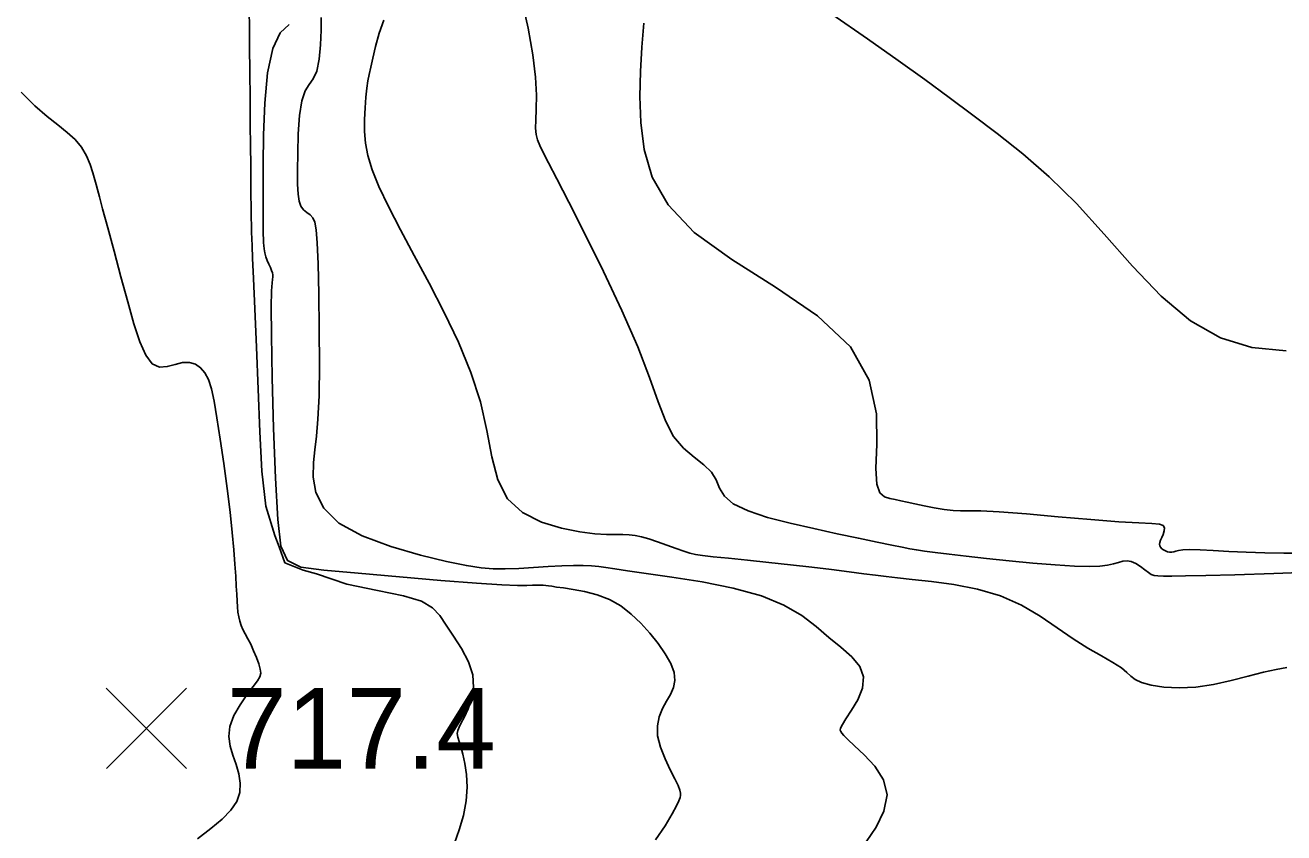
# Model space of a CAD drawing. Extents: x 2566142 to 2571431, y 418755 to 421584.
# Drawn here: x 2566568.3 to 2566803.1, y 419415.7 to 419566.4 of the extents above; entities that cross this region are included whole.
import ezdxf

# ---------------------------------------------------------------- set-up
doc = ezdxf.new("R2010")
doc.units = 0
for name, color, linetype in [('Contour_ADS_Major', 7, 'Continuous'), ('Contour_ADS_Minor', 7, 'Continuous'), ('Contour_ADS_Spot_Elevation', 7, 'Continuous')]:
    doc.layers.add(name, color=color, linetype=linetype)

# ---------------------------------------------------------------- blocks, each defined once
blk = doc.blocks.new('S750')
at = {"layer": 'Contour_ADS_Spot_Elevation'}
for p, q in [((-0.5, 0.498), (0.5, -0.498)), ((-0.498, -0.5), (0.498, 0.5))]:
    blk.add_line(p, q, dxfattribs=at)

msp = doc.modelspace()

# ---------------------------------------------------------------- linework, layer by layer
at = {"layer": 'Contour_ADS_Major'}
for points in [[(2566610.09, 419568.81), (2566610.11, 419566.21), (2566610.15, 419562.38), (2566610.19, 419557.71), (2566610.23, 419552.72), (2566610.28, 419547.95)], [(2566683.68, 419566.78), (2566683.33, 419562.33), (2566683.07, 419557.78), (2566682.97, 419553.1), (2566683.15, 419548.25), (2566683.77, 419543.23), (2566685.28, 419538.08), (2566688.21, 419532.89), (2566693.09, 419527.75), (2566700.12, 419522.68), (2566708.24, 419517.56), (2566716.07, 419512.2), (2566722.23, 419506.42), (2566725.73, 419500.18), (2566727.08, 419493.93), (2566727.19, 419488.25), (2566726.96, 419483.73), (2566727.13, 419480.79), (2566727.73, 419479.17), (2566728.59, 419478.42), (2566729.57, 419478.13), (2566730.56, 419477.91)], [(2566610.28, 419547.95), (2566610.32, 419543.81), (2566610.36, 419540.3), (2566610.39, 419537.32), (2566610.41, 419534.76), (2566610.44, 419532.53), (2566610.46, 419530.61), (2566610.48, 419529), (2566610.51, 419527.71), (2566610.55, 419526.63), (2566610.61, 419525.25), (2566610.72, 419522.97), (2566610.9, 419519.18), (2566611.15, 419513.48), (2566611.46, 419506.35), (2566611.78, 419498.48), (2566612.08, 419490.56), (2566612.42, 419483.21), (2566613.18, 419476.69), (2566614.86, 419471.2), (2566615.68, 419469.11), (2566616.75, 419466.11), (2566620.12, 419464.72), (2566622.64, 419464.03), (2566628.31, 419462.16), (2566634.03, 419460.93), (2566638.89, 419459.97), (2566642.21, 419458.94), (2566644.29, 419457.72), (2566645.65, 419456.27), (2566646.83, 419454.51), (2566648.22, 419452.42), (2566649.69, 419450.1), (2566650.96, 419447.65), (2566651.77, 419445.21), (2566651.92, 419442.88), (2566651.57, 419440.75), (2566650.92, 419438.9), (2566650.22, 419437.39), (2566649.63, 419436.28), (2566649.22, 419435.48), (2566648.97, 419434.85), (2566648.89, 419434.27), (2566648.99, 419433.61), (2566649.22, 419432.81), (2566649.55, 419431.76), (2566649.93, 419430.4), (2566650.32, 419428.67), (2566650.63, 419426.6), (2566650.74, 419424.26), (2566650.56, 419421.69), (2566650.03, 419418.98), (2566649.25, 419416.3), (2566648.37, 419413.82)], [(2566730.56, 419477.91), (2566731.61, 419477.69), (2566732.82, 419477.43), (2566734.26, 419477.13), (2566735.99, 419476.77), (2566737.87, 419476.4), (2566739.72, 419476.08), (2566741.37, 419475.87), (2566742.75, 419475.81), (2566744.29, 419475.81), (2566746.53, 419475.78), (2566750.01, 419475.6), (2566755.05, 419475.22), (2566761.01, 419474.71), (2566767.05, 419474.18), (2566772.28, 419473.77), (2566776.05, 419473.55), (2566778.48, 419473.45), (2566779.88, 419473.34), (2566780.57, 419473.1), (2566780.81, 419472.66), (2566780.78, 419472.06), (2566780.57, 419471.42), (2566780.31, 419470.81), (2566780.09, 419470.31), (2566779.96, 419469.92), (2566779.9, 419469.59), (2566779.95, 419469.3), (2566780.1, 419469.01), (2566780.34, 419468.74), (2566780.65, 419468.51), (2566781.01, 419468.32), (2566781.39, 419468.19), (2566781.78, 419468.13), (2566782.17, 419468.12), (2566782.55, 419468.18), (2566782.93, 419468.3), (2566783.44, 419468.44), (2566784.26, 419468.54), (2566785.56, 419468.58), (2566787.46, 419468.52), (2566789.9, 419468.39), (2566792.8, 419468.23), (2566796.05, 419468.08), (2566799.53, 419467.98), (2566803.06, 419467.93), (2566806.42, 419467.92)]]:
    msp.add_lwpolyline(points, dxfattribs=at)
at = {"layer": 'Contour_ADS_Minor'}
for points in [[(2566660.93, 419571.05), (2566662.1, 419565.82), (2566663.01, 419560.87), (2566663.5, 419556.7), (2566663.66, 419553.35), (2566663.62, 419550.72), (2566663.53, 419548.71), (2566663.51, 419547.21), (2566663.62, 419546.04), (2566663.87, 419545.02), (2566664.29, 419543.96), (2566664.92, 419542.65), (2566665.91, 419540.71), (2566667.44, 419537.77), (2566669.68, 419533.42), (2566672.7, 419527.46), (2566676.16, 419520.46), (2566679.6, 419513.19), (2566682.57, 419506.4), (2566684.77, 419500.71), (2566686.39, 419496.12), (2566687.77, 419492.48), (2566689.26, 419489.66), (2566691.08, 419487.5), (2566693.06, 419485.81), (2566694.9, 419484.39), (2566696.33, 419483.03), (2566697.18, 419481.58), (2566697.82, 419480.06), (2566698.72, 419478.54), (2566700.38, 419477.1), (2566703.14, 419475.78), (2566706.79, 419474.59), (2566711, 419473.5), (2566715.43, 419472.49), (2566719.74, 419471.55), (2566723.73, 419470.71), (2566727.2, 419469.98)], [(2566623.49, 419567.83), (2566623.51, 419565.45), (2566623.4, 419562.72)], [(2566718.77, 419568.48), (2566725.39, 419563.85), (2566731.14, 419559.83), (2566736.11, 419556.25), (2566740.64, 419552.92), (2566745.05, 419549.63), (2566749.62, 419546.19), (2566754.38, 419542.4), (2566759.31, 419538.1), (2566764.38, 419533.11), (2566769.56, 419527.39), (2566774.84, 419521.43), (2566780.22, 419515.83), (2566785.68, 419511.23), (2566791.26, 419508.08), (2566797.14, 419506.3), (2566803.51, 419505.65)], [(2566617.56, 419566.53), (2566615.87, 419564.99), (2566614.46, 419562.08), (2566613.52, 419557.52), (2566612.99, 419551.88), (2566612.76, 419545.92), (2566612.68, 419540.41), (2566612.66, 419535.95), (2566612.66, 419532.55), (2566612.68, 419530.07), (2566612.69, 419528.37), (2566612.71, 419527.28), (2566612.72, 419526.63), (2566612.73, 419526.21), (2566612.76, 419525.81), (2566612.81, 419525.3), (2566612.89, 419524.66), (2566613.02, 419523.95), (2566613.21, 419523.22), (2566613.46, 419522.5), (2566613.75, 419521.82), (2566614.03, 419521.21), (2566614.26, 419520.67), (2566614.42, 419520.23), (2566614.49, 419519.83), (2566614.5, 419519.43), (2566614.45, 419518.99), (2566614.35, 419518.34), (2566614.25, 419516.86)], [(2566635.19, 419567.36), (2566634.35, 419564.94), (2566633.67, 419562.45), (2566633.14, 419560.24), (2566632.74, 419558.55), (2566632.46, 419557.23), (2566632.24, 419556.02), (2566632.04, 419554.66), (2566631.85, 419552.96), (2566631.69, 419550.97), (2566631.6, 419548.81), (2566631.61, 419546.6), (2566631.79, 419544.4), (2566632.22, 419542.07), (2566633.02, 419539.44), (2566634.28, 419536.31), (2566636.08, 419532.56), (2566638.32, 419528.22), (2566640.88, 419523.42), (2566643.64, 419518.25), (2566646.45, 419512.82), (2566649.12, 419507.25), (2566651.45, 419501.64), (2566653.25, 419496.12), (2566654.41, 419490.81), (2566655.32, 419485.9), (2566656.44, 419481.59), (2566658.25, 419478.07), (2566661.08, 419475.47), (2566664.6, 419473.69), (2566668.32, 419472.55), (2566671.76, 419471.88), (2566674.54, 419471.53), (2566676.71, 419471.39), (2566678.39, 419471.37), (2566679.76, 419471.38), (2566680.94, 419471.34), (2566682.06, 419471.21), (2566683.24, 419470.97), (2566684.62, 419470.58), (2566686.25, 419470.04), (2566688.01, 419469.42), (2566689.71, 419468.81), (2566691.17, 419468.29), (2566692.29, 419467.92), (2566693.34, 419467.67), (2566694.67, 419467.47), (2566696.63, 419467.25), (2566699.48, 419466.96), (2566703.03, 419466.61), (2566706.99, 419466.2), (2566711.08, 419465.76), (2566715.03, 419465.3), (2566718.7, 419464.85), (2566721.97, 419464.43), (2566724.72, 419464.07), (2566726.92, 419463.78), (2566728.9, 419463.54), (2566731.04, 419463.3), (2566733.76, 419463.02), (2566737.33, 419462.64), (2566741.52, 419462.08), (2566745.94, 419461.21), (2566750.25, 419459.93), (2566754.15, 419458.19), (2566757.64, 419456.13), (2566760.82, 419453.98), (2566763.77, 419451.95), (2566766.54, 419450.19), (2566769.05, 419448.73), (2566771.16, 419447.51)], [(2566623.4, 419562.72), (2566623.13, 419560.04), (2566622.68, 419557.84), (2566622.03, 419556.38), (2566621.27, 419555.31), (2566620.53, 419554.13), (2566619.9, 419552.32), (2566619.47, 419549.55), (2566619.24, 419546.13), (2566619.13, 419542.55), (2566619.1, 419539.3), (2566619.12, 419536.76), (2566619.21, 419534.89), (2566619.4, 419533.56), (2566619.74, 419532.63), (2566620.24, 419531.98), (2566620.84, 419531.47), (2566621.44, 419531), (2566621.96, 419530.45), (2566622.34, 419529.66), (2566622.6, 419528.25), (2566622.78, 419525.79), (2566622.92, 419521.88), (2566623.06, 419516.29), (2566623.16, 419509.72), (2566623.19, 419503.07), (2566623.11, 419497.24), (2566622.9, 419492.89), (2566622.61, 419489.72), (2566622.31, 419487.21), (2566622.08, 419484.81), (2566622.04, 419482.12), (2566622.54, 419479.21), (2566623.99, 419476.28), (2566626.8, 419473.53), (2566631.17, 419471.14), (2566636.5, 419469.14), (2566642.01, 419467.55), (2566646.91, 419466.37), (2566650.59, 419465.59), (2566653.33, 419465.15), (2566655.58, 419464.98), (2566657.8, 419464.98), (2566660.35, 419465.08), (2566663.11, 419465.24), (2566665.87, 419465.4), (2566668.42, 419465.54), (2566670.58, 419465.6), (2566672.38, 419465.6), (2566673.93, 419465.53), (2566675.3, 419465.4), (2566676.63, 419465.22), (2566678.28, 419464.97), (2566680.64, 419464.6), (2566684.12, 419464.1), (2566688.93, 419463.43), (2566694.57, 419462.54), (2566700.37, 419461.41), (2566705.63, 419459.97), (2566709.84, 419458.22), (2566713.14, 419456.26), (2566715.82, 419454.21), (2566718.19, 419452.21), (2566720.47, 419450.35), (2566722.47, 419448.57), (2566723.96, 419446.76), (2566724.68, 419444.83), (2566724.47, 419442.72), (2566723.61, 419440.58), (2566722.46, 419438.62), (2566721.4, 419437.03), (2566720.73, 419435.94), (2566720.41, 419435.28), (2566720.35, 419434.89), (2566720.44, 419434.63), (2566720.61, 419434.34), (2566720.99, 419433.89), (2566721.74, 419433.16), (2566723, 419432), (2566724.82, 419430.32), (2566726.79, 419428.16), (2566728.38, 419425.63), (2566729.07, 419422.8), (2566728.49, 419419.79), (2566727.02, 419416.79), (2566725.19, 419414.05)], [(2566567.57, 419553.91), (2566570.08, 419551.35), (2566572.38, 419549.39), (2566574.41, 419547.79), (2566576.15, 419546.4), (2566577.61, 419545.07), (2566578.8, 419543.65), (2566579.73, 419542.05), (2566580.43, 419540.39), (2566580.94, 419538.84), (2566581.28, 419537.58), (2566581.52, 419536.68), (2566581.77, 419535.77), (2566582.13, 419534.41), (2566582.74, 419532.12), (2566583.69, 419528.62), (2566584.87, 419524.23), (2566586.16, 419519.46), (2566587.43, 419514.81), (2566588.59, 419510.72), (2566589.69, 419507.35), (2566590.8, 419504.83), (2566592, 419503.24), (2566593.35, 419502.63), (2566594.79, 419502.71), (2566596.26, 419503.11), (2566597.66, 419503.47), (2566598.93, 419503.5), (2566600.05, 419503.17), (2566601.02, 419502.5), (2566601.83, 419501.54), (2566602.47, 419500.28), (2566603.02, 419498.59), (2566603.52, 419496.28), (2566604.06, 419493.17), (2566604.67, 419489.2), (2566605.33, 419484.67), (2566605.96, 419479.99), (2566606.5, 419475.57), (2566606.92, 419471.75), (2566607.22, 419468.52), (2566607.42, 419465.83), (2566607.57, 419463.6), (2566607.67, 419461.76), (2566607.75, 419460.24), (2566607.82, 419458.97), (2566607.9, 419457.88), (2566607.99, 419456.92), (2566608.13, 419456.05), (2566608.31, 419455.23), (2566608.57, 419454.45), (2566608.92, 419453.67), (2566609.35, 419452.86), (2566609.83, 419451.95), (2566610.36, 419450.91), (2566610.91, 419449.72), (2566611.43, 419448.46), (2566611.86, 419447.27), (2566612.15, 419446.25), (2566612.23, 419445.5), (2566612.07, 419444.84), (2566611.6, 419444.08), (2566610.8, 419443.02), (2566609.66, 419441.5), (2566608.38, 419439.65), (2566607.23, 419437.62), (2566606.47, 419435.59), (2566606.27, 419433.7), (2566606.53, 419431.91), (2566607.05, 419430.2)], [(2566614.25, 419516.86), (2566614.19, 419513.84), (2566614.22, 419508.55), (2566614.38, 419500.62), (2566614.64, 419491.24), (2566615, 419481.92), (2566615.43, 419474.19), (2566616.01, 419469.21), (2566617.23, 419466.53), (2566619.7, 419465.33), (2566623.99, 419464.76), (2566630.42, 419464.16), (2566638.09, 419463.48), (2566645.85, 419462.83), (2566652.51, 419462.31), (2566657.2, 419462.02), (2566660.14, 419461.91), (2566661.86, 419461.91), (2566662.9, 419461.95), (2566663.7, 419461.97), (2566664.37, 419461.97), (2566664.94, 419461.95), (2566665.44, 419461.9), (2566665.94, 419461.83), (2566666.55, 419461.74), (2566667.42, 419461.6), (2566668.7, 419461.42), (2566670.49, 419461.16), (2566672.64, 419460.77), (2566674.96, 419460.17), (2566677.27, 419459.28), (2566679.39, 419458.06), (2566681.34, 419456.56), (2566683.13, 419454.85), (2566684.8, 419453), (2566686.35, 419451.08), (2566687.7, 419449.16), (2566688.74, 419447.33), (2566689.36, 419445.65), (2566689.48, 419444.17), (2566689.21, 419442.84), (2566688.65, 419441.57), (2566687.94, 419440.29), (2566687.2, 419438.92), (2566686.58, 419437.41), (2566686.22, 419435.72), (2566686.26, 419433.82), (2566686.8, 419431.7), (2566687.66, 419429.53), (2566688.63, 419427.49), (2566689.49, 419425.79), (2566690.07, 419424.55), (2566690.4, 419423.71), (2566690.53, 419423.15), (2566690.54, 419422.73), (2566690.47, 419422.33), (2566690.25, 419421.74), (2566689.78, 419420.79), (2566688.96, 419419.26), (2566687.7, 419417.06), (2566685.86, 419414.46)], [(2566727.2, 419469.98), (2566729.95, 419469.42), (2566731.89, 419469.02), (2566733.3, 419468.75), (2566734.55, 419468.53), (2566736.03, 419468.31), (2566738.05, 419468.04), (2566740.66, 419467.71), (2566743.84, 419467.33), (2566747.59, 419466.92), (2566751.83, 419466.48), (2566756.24, 419466.07), (2566760.44, 419465.73), (2566764.05, 419465.51), (2566766.8, 419465.44), (2566768.78, 419465.51), (2566770.21, 419465.68), (2566771.29, 419465.92), (2566772.21, 419466.19), (2566773.04, 419466.41), (2566773.83, 419466.5), (2566774.63, 419466.37), (2566775.49, 419465.98), (2566776.34, 419465.41), (2566777.14, 419464.8), (2566777.82, 419464.28), (2566778.35, 419463.94), (2566778.88, 419463.75), (2566779.57, 419463.67), (2566780.62, 419463.65), (2566782.22, 419463.65), (2566784.72, 419463.67), (2566788.51, 419463.74), (2566793.95, 419463.87), (2566801.2, 419464.1), (2566809.51, 419464.4)], [(2566771.16, 419447.51), (2566772.77, 419446.5), (2566773.82, 419445.66), (2566774.57, 419444.96), (2566775.36, 419444.35), (2566776.53, 419443.8), (2566778.33, 419443.31), (2566780.71, 419442.93), (2566783.54, 419442.77), (2566786.67, 419442.91), (2566789.97, 419443.42), (2566793.27, 419444.16), (2566796.43, 419444.98), (2566799.27, 419445.71), (2566801.67, 419446.23), (2566803.65, 419446.56)], [(2566607.05, 419430.2), (2566607.65, 419428.49), (2566608.16, 419426.76), (2566608.42, 419425.02), (2566608.34, 419423.29), (2566607.79, 419421.61), (2566606.67, 419419.97), (2566605.03, 419418.32), (2566602.94, 419416.56), (2566600.45, 419414.61)]]:
    msp.add_lwpolyline(points, dxfattribs=at)

# ---------------------------------------------------------------- block references
at = {"layer": 'Contour_ADS_Spot_Elevation', "xscale": 15, "yscale": 15}
msp.add_blockref('S750', (2566590.9, 419435.24), dxfattribs=at)

# ---------------------------------------------------------------- texts
at = {"layer": 'Contour_ADS_Spot_Elevation'}
msp.add_text('717.4', height=15, dxfattribs=at).set_placement((2566605.9, 419427.74))

doc.saveas('drawing.dxf')
